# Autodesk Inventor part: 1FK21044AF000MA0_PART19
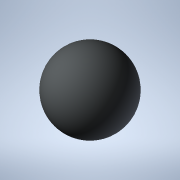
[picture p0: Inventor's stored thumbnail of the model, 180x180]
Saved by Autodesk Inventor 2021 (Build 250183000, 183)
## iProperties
Created: 2025-04
Part Number: 1FK21044AF000MA0_PART19
Material: Generic
Catalog Web Link: www.3dfindit.com
Description: -Servo synchronous motor
Document SubType Name: Modeling
Designer: psAdmin
Mass: 0.137258 g
Surface Area: 1.2868 cm^2
Volume: 0.137258 cm^3
Density: 1 g/cm^3
Appearance: PSOLRGB-212-217-219
Category: PARTsolutions
Title: 1FK21044AF000MA0_PART19
Author: Cadenas PARTsolutions
Comments: Servo synchronous motor
Sending System: PARTsolutions
Preprocessor: ST-DEVELOPER v19.3
PSOL_IDENT_0: {$CADENAS_DATA/23d-libs/siemens_ag/_cat_/39/c4/1fk21044af000ma0.prj},216 {VTYP=3D},{NB=1FK21044AF000
PSOL_IDENT_1: MA0_PART19},{LINA=1FK21044AF000MA0_PART19},{NN=1FK21044AF000MA0_PART19},{NOPRJ=TRUE},{DATE=19.08.202
PSOL_IDENT_2: 5 14:00:33},{GEOMDATE=30.07.2025 02:02:22},{VERSION=},{LINEID=10},{WBVAR=},{WBNUMERIC=}  {NB=1FK2104
PSOL_IDENT_3: 4AF000MA0_PART19},{LINA=1FK21044AF000MA0_PART19},{KT=DUMMY},{PREVIEW=../../../_pool_/cb/72/p_d211_xx
PSOL_IDENT_4: _00434j.png},{DESCSHORT=SIMOTICS S-1FK2 HD, SINAMICS S210 3AC 400V-480V, 1.27 Nm, 3000 rpm},{DESCLON
PSOL_IDENT_5: G=SIMOTICS S-1FK2 HD servo motor M0=1.27 Nm; PN = 0.4 kW at nN=3000 rpm (380-480 V); PN = 0.2 kW at
PSOL_IDENT_6: nN=1500 rpm (200-240 V); degree of protection IP64; cylindrical shaft D19x40mm; absolute encoder 22-
PSOL_IDENT_7: bit + 12-bit multiturn (encoder AM22DQC); with OCC interface; plug size M17, rotatable; SIMOTICS S-1
PSOL_IDENT_8: FK2 servomotorfor a wide range of uses in industrial environments. SIMOTICS S‑1FK2 servomotors are c
PSOL_IDENT_9: ompact synchronous motors with a high dynamic performance that set themselves apart as a result of t
PSOL_IDENT_10: heir high power density, degree of protection and overload capability. The motors are available in t
PSOL_IDENT_11: wo variants: as High Dynamic variant (highest dynamic performance as a result of the low intrinsic m
PSOL_IDENT_12: oment of inertia for applications demanding a high dynamic performance with low moved masses) - and
PSOL_IDENT_13: as Compact variant (precise and stable closed-loop control for medium up to large moved masses as a
PSOL_IDENT_14: result of a medium intrinsic moment of inertia). SIMOTICSS‑1FK2 servomotors fully exploit their stre
PSOL_IDENT_15: ngths in a system with the SINAMICSS210 frequency converter and simple connection using the one cabl
PSOL_IDENT_16: e connection (OCC). Advantages include the short control and positioning times, fast and precise cor
PSOL_IDENT_17: rection of disturbing quantities as well as stable control with a high dynamic performance. The serv
PSOL_IDENT_18: o motors can be configured to address a wide range of requirements. For example with and without hol
PSOL_IDENT_19: ding brake, IP64 or IP65 degree of protection, singleturn or multiturn absolute encoders - to name j
PSOL_IDENT_20: ust a few. Further, the servomotors are available in different shaft heights extending from 20 to 10
PSOL_IDENT_21: 0. A shaft sealing ring is available to achieve an IP65 degree of protection and for subsequent moun
PSOL_IDENT_22: ting at the motor or as spare part. SIMOTICS - the optimum motor for each and every motion control a
PSOL_IDENT_23: pplication.},{INTNO=804766906428},{SUPPLIERALTNO=1FK2104-4AF00-0MA0},{MANUID=1FK21044AF000MA0},{MANU
PSOL_IDENT_24: NAME=Siemens},{MANUTYPEDESC=Synchronous motor 1FK2-HD 1.27 NM},{AAU732=SIMOTICS},{AAO057=S-1FK2},{AA
PSOL_IDENT_25: U734=SIMOTICS S-1FK2 HD servo motor M0=1.27 Nm; PN = 0.4 kW at nN=3000 rpm (380-480 V); PN = 0.2 kW
PSOL_IDENT_26: at nN=1500 rpm (200-240 V); degree of protection IP64; cylindrical shaft D19x40mm; absolute encoder
PSOL_IDENT_27: 22-bit + 12-bit multiturn (encoder AM22DQC); with OCC interface; plug size M17, rotatable;},{AAW338=
PSOL_IDENT_28: Synchronous motor 1FK2-HD 1.27 NM},{AAO742=SIMOTICS},{AAO663=4042948693322},{NOCUPEROU=1},{PRICEQUAN
PSOL_IDENT_29: TITY=1},{QUANTITYMIN=1},{QUANTITYINT=1},{CTN=85015100},{COO=DE},{AAO676=1FK2104-4AF00-0MA0},{AAO677=
PSOL_IDENT_30: Siemens AG},{ORDERUNIT=C62},{CONTENTUNIT=C62}
NB: 1FK21044AF000MA0_PART19
NT: Servo synchronous motor
NBSYN: $MANUID._PART19
LINA: 1FK21044AF000MA0_PART19
CATALOG: SIEMENS
PREVIEW: ../../../_pool_/cb/72/p_d211_xx_00434j.png
DESCSHORT: SIMOTICS S-1FK2 HD, SINAMICS S210 3AC 400V-480V, 1.27 Nm, 3000 rpm
DESCLONG: SIMOTICS S-1FK2 HD servo motor M0=1.27 Nm; PN = 0.4 kW at nN=3000 rpm (380-480 V); PN = 0.2 kW at nN=1500 rpm (200-240 V); degree of protection IP64; cylindrica
INTNO: 804766906428
SUPPLIERALTNO: 1FK2104-4AF00-0MA0
MANUID: 1FK21044AF000MA0
MANUNAME: Siemens
MANUTYPEDESC: Synchronous motor 1FK2-HD 1.27 NM
AAU732: SIMOTICS
AAO057: S-1FK2
AAU734: SIMOTICS S-1FK2 HD servo motor M0=1.27 Nm; PN = 0.4 kW at nN=3000 rpm (380-480 V); PN = 0.2 kW at nN=1500 rpm (200-240 V); degree of protection IP64; cylindrica
AAW338: Synchronous motor 1FK2-HD 1.27 NM
AAO742: SIMOTICS
AAO663: 4042948693322.0
NOCUPEROU: 1
PRICEQUANTITY: 1
QUANTITYMIN: 1
QUANTITYINT: 1
CTN: 85015100
COO: DE
ARTICLENO: 1FK21044AF000MA0_PART19
BOMINFO: 1FK21044AF000MA0_PART19
CREATOR: CADENAS GmbH
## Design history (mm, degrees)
feature "2025_04_17_15_01_28_0038"
body "Solid1"
